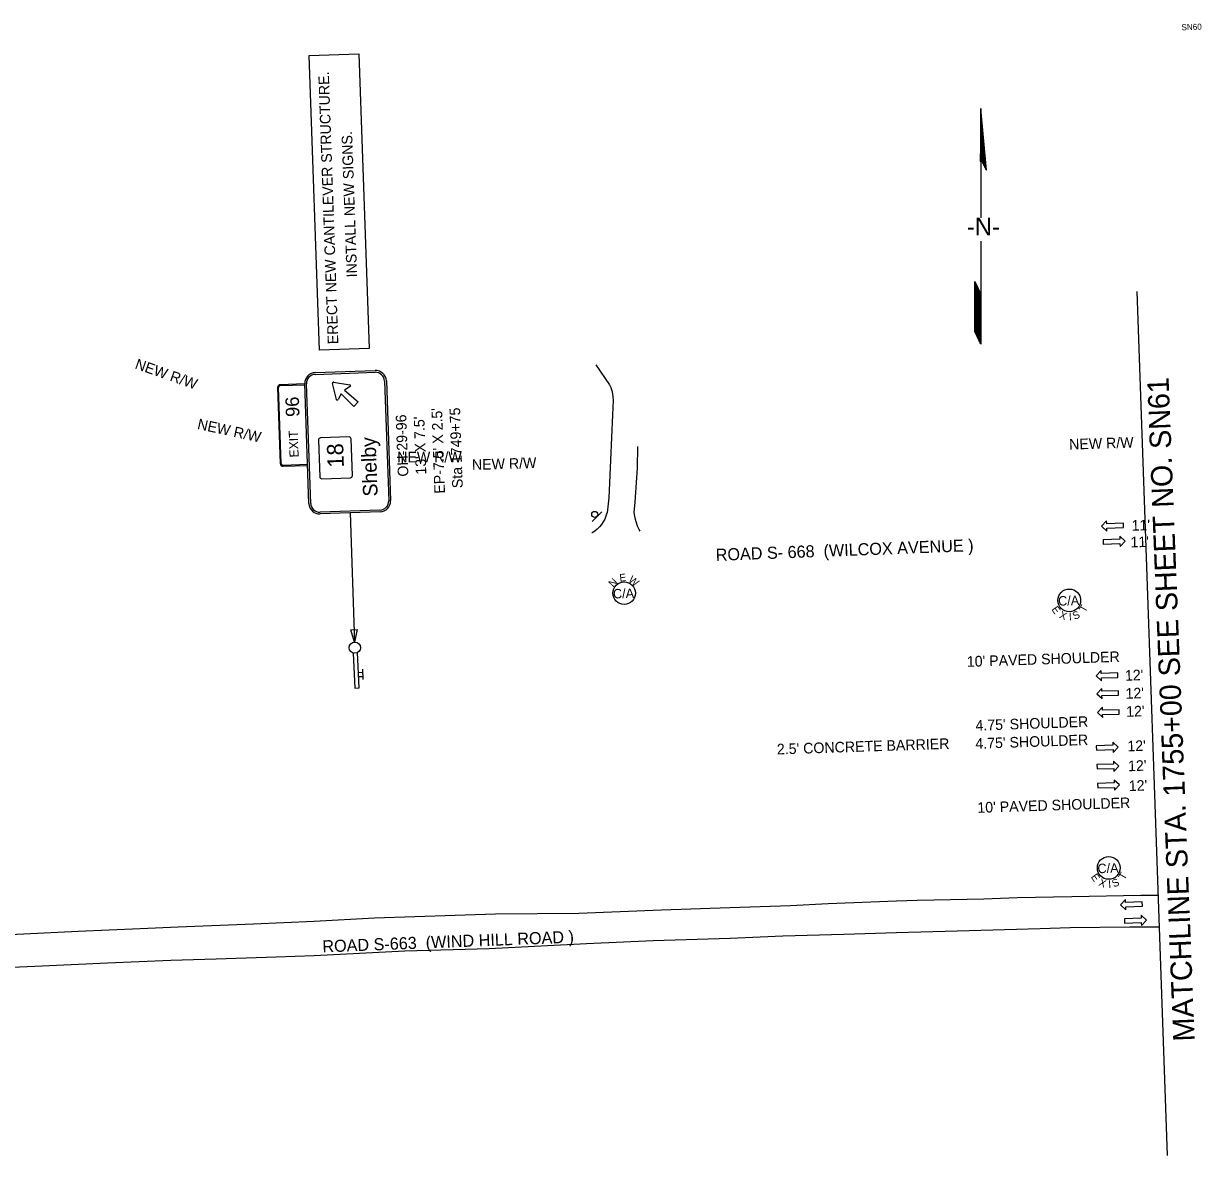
# Model space of a CAD drawing. Extents: x 1820452 to 1822009, y 1192445 to 1193332.
# Drawn here: x 1821231 to 1822009, y 1192583 to 1193332 of the extents above; entities that cross this region are included whole.
import ezdxf

# ---------------------------------------------------------------- set-up
doc = ezdxf.new("R2010")
doc.units = 0
for name, color, linetype in [('RD_EX_Road', 7, 'Continuous'), ('RD_PD_Final_LnLine', 7, 'Continuous'), ('RD_PD_Final_TX', 7, 'Continuous'), ('RD_PD_RW_TX', 7, 'Continuous'), ('RD_SHT_MatchLine', 7, 'Continuous'), ('RD_SHT_TX', 7, 'Continuous'), ('RD_Sketch1', 7, 'Continuous'), ('RD_Sketch10', 7, 'Continuous'), ('RD_Sketch8', 7, 'Continuous'), ('RD_TX_RoadID', 7, 'Continuous'), ('SN_P_Signs', 7, 'Continuous')]:
    doc.layers.add(name, color=color, linetype=linetype)

# ---------------------------------------------------------------- blocks, each defined once
blk = doc.blocks.new('SARRW2')
at = {"layer": 'RD_PD_Final_LnLine'}
blk.add_lwpolyline([(-12, 1.2), (-12, -1.2), (-2.83, -1.2), (-2.83, -2.83), (0, 0), (-2.83, 2.83), (-2.83, 1.2)], close=True, dxfattribs=at)

msp = doc.modelspace()

# ---------------------------------------------------------------- linework, layer by layer
at = {"layer": 'RD_EX_Road'}
for points in [[(1821609.01, 1193106.05), (1821617.99, 1193092.93), (1821618.81, 1193091.1), (1821619.5, 1193089.08), (1821620, 1193087), (1821620.3, 1193084.89), (1821620.41, 1193082.76), (1821620.03, 1193073.02), (1821618.77, 1193042.99), (1821617.64, 1193018.03), (1821616.35, 1193008.1), (1821616.3, 1193007.91), (1821615.65, 1193005.94), (1821614.82, 1193004.03), (1821613.82, 1193002.21), (1821612.64, 1193000.49), (1821611.31, 1192998.9), (1821609.84, 1192997.43), (1821608.23, 1192996.12), (1821606.5, 1192994.96), (1821606.37, 1192994.89)], [(1821638.31, 1192995.99), (1821637.64, 1192997.15), (1821636.61, 1192999.27), (1821635.77, 1193001.48), (1821635.12, 1193003.74), (1821634.65, 1193006.05), (1821634.39, 1193008.39), (1821634.91, 1193015.3), (1821636.56, 1193037.84), (1821636.76, 1193052.12)], [(1821980.66, 1192755.06), (1821969.44, 1192754.91), (1821923.64, 1192754.13), (1821887.7, 1192753.38), (1821865.63, 1192752.65), (1821843.55, 1192752.12), (1821821.47, 1192751.78), (1821807.78, 1192751.31), (1821762.56, 1192749.48), (1821737.75, 1192748.22), (1821697.65, 1192746.92), (1821652.4, 1192745.26), (1821597.74, 1192743.15), (1821542.69, 1192742.61), (1821462.6, 1192739.95), (1821422.68, 1192737.81), (1821382.63, 1192736.12), (1821332.79, 1192734.08), (1821307.73, 1192733.05), (1821266.64, 1192731.22), (1821230.79, 1192729.52), (1821202.71, 1192728.07)], [(1821981.4, 1192734.16), (1821962.12, 1192734.14), (1821942.34, 1192733.93), (1821922.56, 1192733.52), (1821902.78, 1192732.92), (1821847.86, 1192731.5), (1821807.78, 1192730.25), (1821773.01, 1192729.23), (1821732.72, 1192728.01), (1821697.71, 1192726.67), (1821646.81, 1192724.93), (1821602.88, 1192723.07), (1821538.36, 1192719.78), (1821482.72, 1192718.19), (1821422.77, 1192715.09), (1821397.54, 1192714.14), (1821357.79, 1192712.91), (1821327.81, 1192711.98), (1821286.04, 1192710.25), (1821237.87, 1192707.98), (1821212.68, 1192706.86)]]:
    msp.add_lwpolyline(points, dxfattribs=at)
at = {"layer": 'RD_SHT_MatchLine'}
msp.add_lwpolyline([(1821966.65, 1193154.63), (1821986.69, 1192583.05)], dxfattribs=at)
at = {"layer": 'RD_Sketch1'}
for p, q in [((1821863.54, 1193275.58), (1821863.33, 1193240.41)), ((1821867.27, 1193234.87), (1821863.54, 1193275.58)), ((1821863.54, 1193240.71), (1821863.54, 1193218.88)), ((1821863.85, 1193241.82), (1821867.27, 1193234.87)), ((1821863.54, 1193218.88), (1821863.54, 1193203.41)), ((1821863.54, 1193187.97), (1821863.54, 1193162.19)), ((1821859.55, 1193147.13), (1821859.55, 1193161.31)), ((1821859.55, 1193161.31), (1821863.54, 1193152.74)), ((1821863.54, 1193162.19), (1821863.54, 1193119.67)), ((1821859.55, 1193128.23), (1821859.55, 1193147.13)), ((1821863.54, 1193119.67), (1821859.55, 1193128.23))]:
    msp.add_line(p, q, dxfattribs=at)
for points in [[(1821863.55, 1193241.02), (1821863.55, 1193275.46)], [(1821863.65, 1193241.28), (1821863.65, 1193274.42)], [(1821863.74, 1193241.53), (1821863.74, 1193273.39)], [(1821863.84, 1193241.79), (1821863.84, 1193272.36)], [(1821863.93, 1193241.64), (1821863.93, 1193271.33)], [(1821864.03, 1193241.45), (1821864.03, 1193270.29)], [(1821864.12, 1193241.26), (1821864.12, 1193269.26)], [(1821864.21, 1193241.07), (1821864.21, 1193268.23)], [(1821864.31, 1193240.87), (1821864.31, 1193267.2)], [(1821863.46, 1193240.76), (1821863.46, 1193261.54)], [(1821864.4, 1193240.68), (1821864.4, 1193266.16)], [(1821864.5, 1193240.49), (1821864.5, 1193265.13)], [(1821864.59, 1193240.3), (1821864.59, 1193264.1)], [(1821864.69, 1193240.11), (1821864.69, 1193263.07)], [(1821864.78, 1193239.92), (1821864.78, 1193262.03)], [(1821864.88, 1193239.72), (1821864.88, 1193261)], [(1821864.97, 1193239.53), (1821864.97, 1193259.97)], [(1821865.07, 1193239.34), (1821865.07, 1193258.94)], [(1821865.16, 1193239.15), (1821865.16, 1193257.9)], [(1821865.25, 1193238.96), (1821865.25, 1193256.87)], [(1821865.35, 1193238.77), (1821865.35, 1193255.84)], [(1821865.44, 1193238.57), (1821865.44, 1193254.81)], [(1821865.54, 1193238.38), (1821865.54, 1193253.77)], [(1821865.63, 1193238.19), (1821865.63, 1193252.74)], [(1821865.73, 1193238), (1821865.73, 1193251.71)], [(1821863.36, 1193240.5), (1821863.36, 1193245.64)], [(1821865.82, 1193237.81), (1821865.82, 1193250.68)], [(1821865.92, 1193237.62), (1821865.92, 1193249.64)], [(1821866.01, 1193237.42), (1821866.01, 1193248.61)], [(1821866.1, 1193237.23), (1821866.1, 1193247.58)], [(1821866.2, 1193237.04), (1821866.2, 1193246.55)], [(1821866.29, 1193236.85), (1821866.29, 1193245.51)], [(1821866.39, 1193236.66), (1821866.39, 1193244.48)], [(1821866.48, 1193236.47), (1821866.48, 1193243.45)], [(1821866.58, 1193236.27), (1821866.58, 1193242.41)], [(1821866.67, 1193236.08), (1821866.67, 1193241.38)], [(1821866.77, 1193235.89), (1821866.77, 1193240.35)], [(1821866.86, 1193235.7), (1821866.86, 1193239.32)], [(1821866.96, 1193235.51), (1821866.96, 1193238.28)], [(1821867.05, 1193235.32), (1821867.05, 1193237.25)], [(1821867.14, 1193235.12), (1821867.14, 1193236.22)], [(1821867.24, 1193234.93), (1821867.24, 1193235.19)], [(1821859.63, 1193128.07), (1821859.63, 1193161.14)], [(1821859.72, 1193127.87), (1821859.72, 1193160.94)], [(1821859.82, 1193127.66), (1821859.82, 1193160.74)], [(1821859.91, 1193127.46), (1821859.91, 1193160.53)], [(1821860, 1193127.26), (1821860, 1193160.33)], [(1821860.1, 1193127.06), (1821860.1, 1193160.13)], [(1821860.19, 1193126.85), (1821860.19, 1193159.92)], [(1821860.29, 1193126.65), (1821860.29, 1193159.72)], [(1821860.38, 1193126.45), (1821860.38, 1193159.52)], [(1821860.48, 1193126.25), (1821860.48, 1193159.32)], [(1821860.57, 1193126.04), (1821860.57, 1193159.11)], [(1821860.67, 1193125.84), (1821860.67, 1193158.91)], [(1821860.76, 1193125.64), (1821860.76, 1193158.71)], [(1821860.85, 1193125.44), (1821860.85, 1193158.51)], [(1821860.95, 1193125.23), (1821860.95, 1193158.3)], [(1821861.04, 1193125.03), (1821861.04, 1193158.1)], [(1821861.14, 1193124.83), (1821861.14, 1193157.9)], [(1821861.23, 1193124.62), (1821861.23, 1193157.7)], [(1821861.33, 1193124.42), (1821861.33, 1193157.49)], [(1821861.42, 1193124.22), (1821861.42, 1193157.29)], [(1821861.52, 1193124.02), (1821861.52, 1193157.09)], [(1821861.61, 1193123.81), (1821861.61, 1193156.89)], [(1821861.7, 1193123.61), (1821861.7, 1193156.68)], [(1821861.8, 1193123.41), (1821861.8, 1193156.48)], [(1821861.89, 1193123.21), (1821861.89, 1193156.28)], [(1821861.99, 1193123), (1821861.99, 1193156.07)], [(1821862.08, 1193122.8), (1821862.08, 1193155.87)], [(1821862.18, 1193122.6), (1821862.18, 1193155.67)], [(1821862.27, 1193122.4), (1821862.27, 1193155.47)], [(1821862.37, 1193122.19), (1821862.37, 1193155.26)], [(1821862.46, 1193121.99), (1821862.46, 1193155.06)], [(1821862.56, 1193121.79), (1821862.56, 1193154.86)], [(1821862.65, 1193121.59), (1821862.65, 1193154.66)], [(1821862.74, 1193121.38), (1821862.74, 1193154.45)], [(1821862.84, 1193121.18), (1821862.84, 1193154.25)], [(1821862.93, 1193120.98), (1821862.93, 1193154.05)], [(1821863.03, 1193120.77), (1821863.03, 1193153.85)], [(1821863.12, 1193120.57), (1821863.12, 1193153.64)], [(1821863.22, 1193120.37), (1821863.22, 1193153.44)], [(1821863.31, 1193120.17), (1821863.31, 1193153.24)], [(1821863.41, 1193119.96), (1821863.41, 1193153.04)], [(1821863.5, 1193119.76), (1821863.5, 1193152.83)]]:
    msp.add_lwpolyline(points, dxfattribs=at)
at = {"layer": 'RD_Sketch10'}
msp.add_circle((1821627.71, 1192955), 7.5, dxfattribs=at)
at = {"layer": 'RD_Sketch8'}
for centre in [(1821922.08, 1192950.25), (1821948.11, 1192773.25)]:
    msp.add_circle(centre, 7.5, dxfattribs=at)
at = {"layer": 'SN_P_Signs'}
for p, q in [((1821419.45, 1193310.65), (1821452.23, 1193311.79)), ((1821426.28, 1193115.77), (1821419.45, 1193310.65)), ((1821452.23, 1193311.79), (1821459.07, 1193116.91)), ((1821459.07, 1193116.91), (1821426.28, 1193115.77)), ((1821398.53, 1193091.07), (1821400.3, 1193040.7)), ((1821416.46, 1193093.5), (1821400.27, 1193092.93)), ((1821416.48, 1193092.9), (1821416.46, 1193093.5)), ((1821425.56, 1193056.29), (1821426.41, 1193032)), ((1821445.75, 1193058.35), (1821426.87, 1193057.69)), ((1821447.57, 1193045.04), (1821447.15, 1193057.05)), ((1821448, 1193032.76), (1821447.57, 1193045.04)), ((1821418.33, 1193040.13), (1821402.14, 1193039.56)), ((1821402.16, 1193038.96), (1821418.35, 1193039.53)), ((1821418.35, 1193039.53), (1821418.33, 1193040.13)), ((1821427.81, 1193030.7), (1821446.7, 1193031.36)), ((1821446.47, 1193008.1), (1821449.46, 1192922.66)), ((1821606.48, 1193002.52), (1821612.84, 1193008.89)), ((1821451.98, 1192902.55), (1821454.75, 1192902.68)), ((1821454.64, 1192904.77), (1821454.96, 1192897.83)), ((1821452.11, 1192899.87), (1821454.88, 1192900))]:
    msp.add_line(p, q, dxfattribs=at)
for points in [[(1821423.4, 1193100.95), (1821462.98, 1193102.33)], [(1821423.44, 1193099.75), (1821463.02, 1193101.13)], [(1821469.23, 1193095.35), (1821472, 1193016.2)], [(1821470.43, 1193095.39), (1821473.2, 1193016.24)], [(1821400.9, 1193040.72), (1821399.13, 1193091.09)], [(1821400.29, 1193092.33), (1821416.48, 1193092.9)], [(1821419.23, 1193014.35), (1821416.46, 1193093.5)], [(1821420.43, 1193014.39), (1821417.66, 1193093.54)], [(1821437.36, 1193083.24), (1821434.92, 1193093.82)], [(1821435.59, 1193094.54), (1821446.32, 1193092.85)], [(1821446.56, 1193091.76), (1821442.85, 1193089.3)], [(1821442.85, 1193089.3), (1821451.85, 1193081.58)], [(1821440.65, 1193086.94), (1821438.46, 1193083.08)], [(1821451.85, 1193081.58), (1821448.99, 1193078.51), (1821440.65, 1193086.94)], [(1821466.22, 1193009.99), (1821426.64, 1193008.6)], [(1821466.26, 1193008.79), (1821426.68, 1193007.4)], [(1821448.59, 1192915.38), (1821449.67, 1192892.27), (1821452.46, 1192892.4), (1821451.37, 1192915.69)]]:
    msp.add_lwpolyline(points, dxfattribs=at)
msp.add_lwpolyline([(1821451.09, 1192930.95), (1821449.42, 1192922.66), (1821446.99, 1192930.76)], close=True, dxfattribs=at)
for centre, radius in [((1821608.24, 1193007.15), 2), ((1821449.59, 1192918.95), 3.71)]:
    msp.add_circle(centre, radius, dxfattribs=at)
for centre, radius, start, end in [((1821423.65, 1193093.75), 7.2, 92.00775, 182.00775), ((1821423.65, 1193093.75), 6, 92.00775, 182.00775), ((1821463.23, 1193095.14), 7.2, 2.00775, 92.00775), ((1821463.23, 1193095.14), 6, 2.00775, 92.00775), ((1821400.33, 1193091.13), 1.8, 92.00775, 182.00775), ((1821400.33, 1193091.13), 1.2, 92.00775, 182.00775), ((1821435.5, 1193093.95), 0.6, 81.02715, 192.98845), ((1821446.23, 1193092.26), 0.6, 303.56175, 81.02715), ((1821437.94, 1193083.37), 0.6, 192.98845, 330.45385), ((1821426.91, 1193056.34), 1.35, 92.00775, 182.00775), ((1821445.8, 1193057), 1.35, 2.01015, 92.01015), ((1821402.1, 1193040.76), 1.8, 182.00775, 272.00775), ((1821402.1, 1193040.76), 1.2, 182.00775, 272.00775), ((1821446.65, 1193032.71), 1.35, 272.01015, 2.01015), ((1821427.76, 1193032.05), 1.35, 182.00775, 272.01015), ((1821426.43, 1193014.6), 7.2, 182.00775, 272.00775), ((1821426.43, 1193014.6), 6, 182.00775, 272.00775), ((1821466, 1193015.99), 6, 272.00775, 2.00775), ((1821466, 1193015.99), 7.2, 272.00775, 2.00775)]:
    msp.add_arc(centre, radius, start, end, dxfattribs=at)

# ---------------------------------------------------------------- block references
at = {"layer": 'RD_PD_Final_LnLine'}
for p, xscale, yscale, rotation in [((1821943.47, 1192999.32), 1.2000000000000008, 1.200000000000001, -177.99217052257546), ((1821958.91, 1192989.35), 1.200000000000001, 1.2000000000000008, 2.007829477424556), ((1821939.82, 1192900.27), 1.2000000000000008, 1.200000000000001, -177.99217052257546), ((1821940.23, 1192888.54), 1.2000000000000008, 1.200000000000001, -177.99217052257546), ((1821940.67, 1192876), 1.2000000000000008, 1.200000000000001, -177.99217052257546), ((1821954.37, 1192853.2), 1.200000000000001, 1.2000000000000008, 2.007829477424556), ((1821954.81, 1192840.67), 1.200000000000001, 1.2000000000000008, 2.007829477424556), ((1821955.25, 1192828.13), 1.200000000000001, 1.2000000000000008, 2.007829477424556), ((1821955.95, 1192748.89), 1.2000000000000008, 1.200000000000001, -177.99217052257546), ((1821973.01, 1192738.69), 1.200000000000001, 1.2000000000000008, 2.007829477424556)]:
    msp.add_blockref('SARRW2', p, dxfattribs=dict(at, xscale=xscale, yscale=yscale, rotation=rotation))

# ---------------------------------------------------------------- texts
at = {"layer": 'RD_PD_Final_TX'}
for s, rotation, p in [("11'", 1.28147, (1821963.35, 1192996.34)), ("11'", 1.28147, (1821962.62, 1192985.3)), ("10' PAVED SHOULDER", 1.88215, (1821854.42, 1192906.27)), ("12'", 2.21446, (1821958.99, 1192897.04)), ("12'", 2.21446, (1821959.4, 1192885.11)), ("12'", 2.21446, (1821959.82, 1192873.18)), ("4.75' SHOULDER", 2.00775, (1821860.15, 1192864.03)), ("4.75' SHOULDER", 2.00775, (1821860.04, 1192852.02)), ("2.5' CONCRETE BARRIER", 1.88215, (1821728.8, 1192848.31)), ("12'", 2.21446, (1821960.62, 1192850.33)), ("12'", 2.21446, (1821961.08, 1192837.18)), ("12'", 2.21446, (1821961.54, 1192824.04)), ("10' PAVED SHOULDER", 1.88215, (1821861.38, 1192809.66))]:
    msp.add_text(s, height=7, rotation=rotation, dxfattribs=at).set_placement(p)
at = {"layer": 'RD_PD_RW_TX'}
for rotation, p in [(340.7466, (1821303.68, 1193103.78)), (347.72298, (1821345.04, 1193063.74)), (1.87004, (1821922.07, 1193049.97)), (0.02532, (1821477.63, 1193041.53)), (1.87004, (1821527.15, 1193036.45))]:
    msp.add_text('NEW R/W', height=7, rotation=rotation, dxfattribs=at).set_placement(p)
at = {"layer": 'RD_SHT_TX'}
for s, height, rotation, p in [('SN60', 4, 2.03127, (1821996.33, 1193327.35)), ('MATCHLINE STA. 1755+00 SEE SHEET NO. SN61', 14.1726, 92.25659, (1822005.02, 1192658.72))]:
    msp.add_text(s, height=height, rotation=rotation, dxfattribs=at).set_placement(p)
at = {"layer": 'RD_Sketch1'}
msp.add_text('-N-', height=11.811, rotation=0, dxfattribs=at).set_placement((1821854.35, 1193191.67))
at = {"layer": 'RD_Sketch10'}
for s, height, rotation, p in [('N', 5, 46.87751, (1821620.45, 1192958.58)), ('E', 5, 6.3408, (1821624.87, 1192962.61)), ('W', 5, 321.31036, (1821630.05, 1192963.04)), ('C/A', 6.25, 2.00775, (1821620.41, 1192951.46))]:
    msp.add_text(s, height=height, rotation=rotation, dxfattribs=at).set_placement(p)
at = {"layer": 'RD_Sketch8'}
for s, height, rotation, p in [('C/A', 6.25, 2.00775, (1821914.78, 1192946.72)), ('T', 5, 60.19289, (1821932.57, 1192941.91)), ('E', 5, 305.21899, (1821910.06, 1192944.31)), ('X', 5, 337.64836, (1821915.03, 1192938.82)), ('I', 5, 1.80836, (1821921.88, 1192936.99)), ('S', 5, 23.80019, (1821925.53, 1192937.29)), ('C/A', 6.25, 2.00775, (1821940.81, 1192769.71)), ('E', 5, 305.21899, (1821936.08, 1192767.31)), ('T', 5, 60.19289, (1821958.59, 1192764.91)), ('X', 5, 337.64836, (1821941.06, 1192761.82)), ('I', 5, 1.80836, (1821947.91, 1192759.99)), ('S', 5, 23.80019, (1821951.55, 1192760.29))]:
    msp.add_text(s, height=height, rotation=rotation, dxfattribs=at).set_placement(p)
at = {"layer": 'RD_TX_RoadID'}
for s, rotation, p in [('ROAD S- 668  (WILCOX AVENUE )', 2.18099, (1821688.4, 1192976.35)), ('ROAD S-663  (WIND HILL ROAD )', 2.23942, (1821428.28, 1192717.33))]:
    msp.add_text(s, height=8, rotation=rotation, dxfattribs=at).set_placement(p)
at = {"layer": 'SN_P_Signs'}
for s, height, rotation, p in [('ERECT NEW CANTILEVER STRUCTURE.', 7, 92.00783, (1821438.7, 1193119.84)), ('INSTALL NEW SIGNS.', 7, 92.00783, (1821451.15, 1193164.05)), ('96', 9, 92.00775, (1821413.02, 1193071.77)), ('OH-29-96', 7, 92.00783, (1821485.02, 1193032.26)), ("EP-7.5' X 2.5'", 7, 92.00783, (1821509.23, 1193020.98)), ('Sta 1749+75', 7, 92.00783, (1821521.01, 1193024.59)), ("13' X 7.5'", 7, 92.00783, (1821496.88, 1193033.56)), ('EXIT', 6, 92.00775, (1821412.46, 1193044.91)), ('Shelby', 9.6, 92.00775, (1821464.7, 1193019.15)), ('18', 10.8, 92.00775, (1821442.4, 1193038.29))]:
    msp.add_text(s, height=height, rotation=rotation, dxfattribs=at).set_placement(p)

doc.saveas('drawing.dxf')
